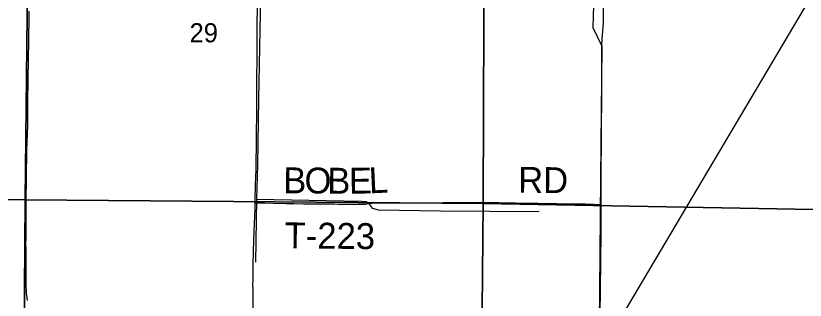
# Model space of a CAD drawing. Extents: x 1443599 to 1910620, y 1028088 to 1361369.
# Drawn here: x 1626102 to 1635252, y 1256148 to 1259443 of the extents above; entities that cross this region are included whole.
import ezdxf

# ---------------------------------------------------------------- set-up
doc = ezdxf.new("R2010")
doc.units = 0
for name, color, linetype in [('GM_X_County_Road', 7, 'Continuous'), ('GM_X_Minor_River', 7, 'Continuous'), ('GM_X_Rail_Line', 7, 'Continuous'), ('GM_X_Section', 7, 'Continuous'), ('GM_X_Section_Text', 7, 'Continuous'), ('GM_X_Township_Road', 7, 'Continuous'), ('GM_X_Township_Road_Text', 7, 'Continuous')]:
    doc.layers.add(name, color=color, linetype=linetype)

msp = doc.modelspace()

# ---------------------------------------------------------------- linework, layer by layer
at = {"layer": 'GM_X_County_Road'}
for points in [[(1628877.2, 1257277), (1628878, 1257307.9), (1628882.3, 1257481.8), (1628887.1, 1257665.5), (1628888.5, 1257734.4), (1628889.9, 1257819.7), (1628890.5, 1257868.1), (1628891.2, 1257917.8), (1628892.1, 1258020.1), (1628893, 1258127.8), (1628894.6, 1258262.4), (1628895.2, 1258337.9), (1628895.6, 1258406.8), (1628895.6, 1258456), (1628895.8, 1258531.5), (1628896.3, 1258622.5), (1628897.8, 1258723.7), (1628898.6, 1258940.2), (1628900.1, 1259166.7), (1628901, 1259334.2), (1628904.1, 1259554.2)], [(1628853.3, 1256027.8), (1628852.3, 1256172.3), (1628851.9, 1256277.4), (1628851.7, 1256326.7), (1628851.9, 1256382.5), (1628852.5, 1256438.3), (1628854.8, 1256559.8), (1628858.5, 1256707.6), (1628863.1, 1256848.7), (1628869.7, 1257042.3), (1628871.9, 1257107.9), (1628875.7, 1257219.4), (1628876.6, 1257258.7), (1628877.2, 1257277)]]:
    msp.add_lwpolyline(points, dxfattribs=at)
at = {"layer": 'GM_X_Minor_River'}
for points in [[(1628951.4, 1260519.6), (1628941.4, 1259879.3), (1628914.7, 1258475.2), (1628904.3, 1257715), (1628892.7, 1257317.9), (1628878.8, 1256587.8)], [(1628941.4, 1259879.3), (1629512.3, 1259874.7), (1630755.9, 1259855.4), (1632045.4, 1259829.3), (1632804.4, 1259819.1), (1632790.6, 1259305.6), (1632896.7, 1259090.9), (1632879.7, 1257566.3), (1632870.9, 1256679.6), (1632859.9, 1255471.9), (1632849.9, 1254627.4)], [(1628892.7, 1257317.9), (1630110.3, 1257297.1), (1630160.2, 1257292.2), (1630195.9, 1257273.4), (1630209.4, 1257243.1), (1630232.3, 1257215.6), (1630306.6, 1257195.1), (1631023.5, 1257181.7), (1632167.2, 1257176.3)]]:
    msp.add_lwpolyline(points, dxfattribs=at)
at = {"layer": 'GM_X_Rail_Line'}
msp.add_lwpolyline([(1628023.8, 1247385.4), (1629401.8, 1249687.9), (1632328.1, 1254610.4), (1636988.2, 1262473.3), (1640103.6, 1267682.6), (1644118.4, 1274411.1), (1645799.9, 1277195.1), (1647368.1, 1279857.7), (1650565.7, 1285234.3), (1651910.4, 1287492.2), (1654330.5, 1291580.9), (1655751.8, 1293975.8)], dxfattribs=at)
at = {"layer": 'GM_X_Section'}
for points in [[(1620879, 1262697.1), (1626269.9, 1262658.4), (1626212, 1257310.8), (1620860.3, 1257406.9)], [(1626269.9, 1262658.4), (1631539, 1262565.5), (1631517.7, 1257269.4), (1626212, 1257310.8)], [(1631539, 1262565.5), (1636955.9, 1262450.6), (1636834.8, 1257171.7), (1631517.7, 1257269.4)], [(1620860.3, 1257406.9), (1626212, 1257310.8), (1626171.3, 1252055), (1620801.8, 1252133.4)], [(1626212, 1257310.8), (1631517.7, 1257269.4), (1631468.2, 1251951.7), (1626171.3, 1252055)], [(1631517.7, 1257269.4), (1636834.8, 1257171.7), (1636741.5, 1251880.5), (1631468.2, 1251951.7)]]:
    msp.add_lwpolyline(points, close=True, dxfattribs=at)
at = {"layer": 'GM_X_Township_Road'}
for points in [[(1632886.4, 1257257.7), (1632887.7, 1257404.2), (1632888, 1257486.4), (1632888.2, 1257634.1), (1632888.4, 1257699.7), (1632889.5, 1257929.5), (1632890.5, 1258126.5), (1632893.2, 1258504), (1632894.6, 1258651.7), (1632895.7, 1258897.9), (1632896.5, 1259094.8), (1632899.3, 1259176.7), (1632909.4, 1259307.6), (1632912.4, 1259373), (1632913.7, 1259487.8), (1632913.5, 1259618.8), (1632913, 1259750.1), (1632912.9, 1259897.8), (1632912.9, 1259908.7)], [(1626221.6, 1256640.7), (1626221.6, 1256648), (1626221.5, 1256680.9), (1626221.2, 1256710.4), (1626220.9, 1256743.2), (1626220.6, 1256805.6), (1626221.1, 1256867.9), (1626221.7, 1256963.1), (1626222.1, 1257081.3), (1626221.5, 1257166.4), (1626222.7, 1257268.4), (1626223.1, 1257314.3), (1626224, 1257389.1), (1626224.8, 1257477.4), (1626225.3, 1257526.8), (1626227.2, 1257671.2), (1626229.7, 1257789.3), (1626231.9, 1257887.8), (1626235, 1257982.5), (1626238, 1258068), (1626240.9, 1258178.4), (1626242.2, 1258264.8), (1626242.4, 1258416.1), (1626243.7, 1258515.5), (1626245, 1258633.6), (1626245.6, 1258679.5), (1626246.3, 1258732), (1626247.2, 1258797.5), (1626248.2, 1258856.5), (1626249.6, 1258918.8), (1626251.3, 1259007.5), (1626252.7, 1259089.5), (1626254.7, 1259214.2), (1626255.4, 1259260.2), (1626256.7, 1259345.5), (1626257.1, 1259384.9), (1626257.4, 1259424.3), (1626257.7, 1259496.5)], [(1628877.2, 1257277), (1628891.1, 1257276.7), (1628925.9, 1257276), (1628988.3, 1257274.2), (1629086.8, 1257272.1), (1629234.6, 1257268.5), (1629323.2, 1257266.4), (1629438.1, 1257264.8), (1629553.1, 1257263.4), (1629687.7, 1257262.4), (1629792.8, 1257262.6), (1629838.8, 1257262), (1629911, 1257261.3), (1629986.2, 1257260.9), (1630071.9, 1257260.4), (1630098.2, 1257260.2), (1630130, 1257260), (1630144.3, 1257260.3), (1630156.9, 1257261), (1630170.8, 1257263), (1630196.3, 1257267.4), (1630231.9, 1257273.4), (1630240.2, 1257274.6), (1630247.7, 1257275.6), (1630258.5, 1257276.7), (1630268.7, 1257276.7), (1630284.2, 1257276.8), (1630313.8, 1257277.5), (1630363, 1257277.7), (1630491.1, 1257275.3), (1630576.5, 1257274.6), (1630698, 1257274), (1630760.4, 1257274.5), (1630842.4, 1257275.2), (1630908.1, 1257276.6), (1631009.9, 1257277.6), (1631055.9, 1257278.1), (1631100.9, 1257278), (1631148.4, 1257279.3), (1631183.1, 1257279.8), (1631216.7, 1257280.4)], [(1631216.7, 1257280.4), (1631246.3, 1257281), (1631377.6, 1257280.2), (1631463, 1257279.6), (1631512.2, 1257279.7), (1631594.3, 1257280.1), (1631699.4, 1257279.3), (1631893.2, 1257276.4), (1632047.5, 1257273.5), (1632155.8, 1257270.7), (1632211.6, 1257269.4), (1632372.5, 1257266.9), (1632480.9, 1257265.7), (1632536.7, 1257264.9), (1632622.1, 1257263.9), (1632700.9, 1257263), (1632805.9, 1257259.9), (1632863, 1257258.3), (1632886.4, 1257257.7)], [(1632855.6, 1254609.9), (1632854.3, 1254695.9), (1632855.8, 1254827.2), (1632866.1, 1255401.7), (1632867.2, 1255533), (1632870.3, 1255713.5), (1632879.5, 1256271.6), (1632885.8, 1256928.3), (1632886.3, 1257076.1), (1632885.9, 1257190.9), (1632886.4, 1257257.7)], [(1626239.8, 1256144.5), (1626236.6, 1256155.2), (1626234.9, 1256164.2), (1626232.4, 1256177.1), (1626229.2, 1256199.3), (1626226.6, 1256225), (1626224.7, 1256257.5), (1626223.6, 1256310), (1626223.1, 1256336.2), (1626223.1, 1256349.4), (1626222.7, 1256382.2), (1626222.3, 1256418.3), (1626222.1, 1256451.1), (1626222, 1256480.6), (1626221.9, 1256516.7), (1626221.9, 1256549.6), (1626221.9, 1256569.2), (1626221.8, 1256611.9), (1626221.6, 1256640.7)]]:
    msp.add_lwpolyline(points, dxfattribs=at)

# ---------------------------------------------------------------- texts
at = {"layer": 'GM_X_Section_Text'}
msp.add_text('29', height=221, rotation=0.00001, dxfattribs=at).set_placement((1628116.9, 1259136))
at = {"layer": 'GM_X_Township_Road_Text'}
for s, rotation, p in [('B', 359.47698, (1629201, 1257388)), ('O', 359.47819, (1629447.4, 1257385.7)), ('B', 359.50147, (1629711.5, 1257383.3)), ('E', 0.87295, (1629965.7, 1257381.2)), ('L', 2.66542, (1630200.4, 1257385)), ('RD', 359.50636, (1631923.9, 1257392.4)), ('T-223', 359.43169, (1629217.2, 1256749.5))]:
    msp.add_text(s, height=300, rotation=rotation, dxfattribs=at).set_placement(p)

doc.saveas('drawing.dxf')
